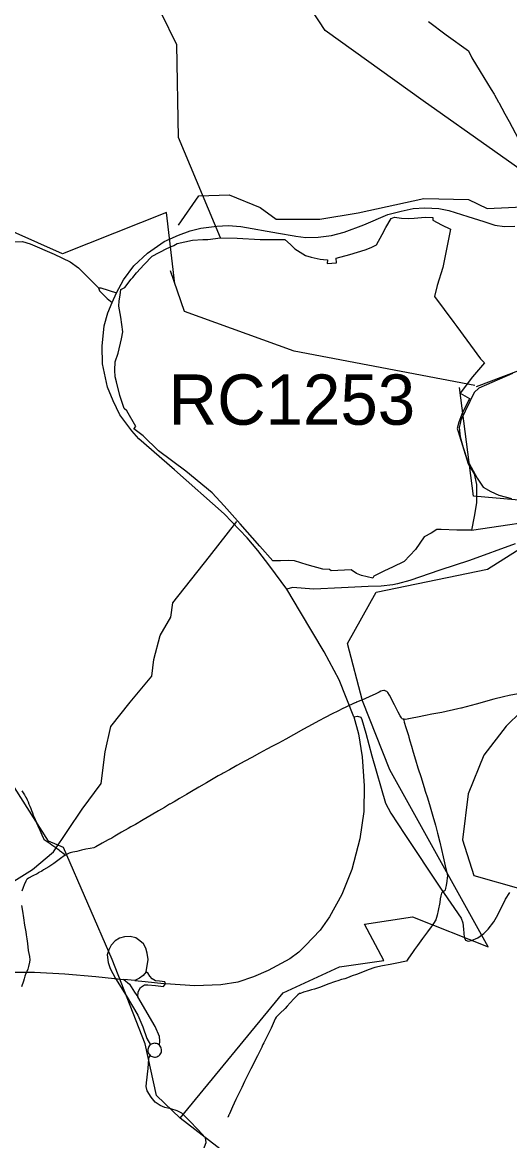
# Model space of a CAD drawing. Extents: x -789162 to -606354, y -1062736 to -945481.
# Drawn here: x -683220 to -681766, y -983825 to -980490 of the extents above; entities that cross this region are included whole.
import ezdxf

# ---------------------------------------------------------------- set-up
doc = ezdxf.new("R2010")
doc.units = 0
for name, color, linetype in [('_SIRSI VZTAHY_CYKLOTRASY MISTNI S', 7, 'Continuous'), ('_SIRSI VZTAHY_SILNICE I TRIDY_NAVRH', 7, 'Continuous'), ('_SIRSI VZTAHY_SILNICE I TRIDY_STAV', 7, 'Continuous'), ('_SIRSI VZTAHY_SILNICE III TRIDY_STAV', 7, 'Continuous'), ('_SIRSI VZTAHY_USES_NRBK_S', 7, 'Continuous'), ('_SIRSI VZTAHY_USES_popis S', 7, 'Continuous'), ('_SIRSI VZTAHY_USES_RBC_S', 7, 'Continuous'), ('_SIRSI VZTAHY_USES_RBK_S', 7, 'Continuous'), ('_SIRSI VZTAHY_VTL PLYNOVOD', 7, 'Continuous')]:
    doc.layers.add(name, color=color, linetype=linetype)

msp = doc.modelspace()

# ---------------------------------------------------------------- linework, layer by layer
at = {"layer": '_SIRSI VZTAHY_CYKLOTRASY MISTNI S'}
for points in [[(-682754.6, -981095.2), (-682693.5, -981007.5), (-682603.3, -981004.8), (-682510.3, -981042), (-682462.5, -981076.6), (-682332.4, -981076.6), (-682218.3, -981058), (-682021.8, -981015.5), (-681889, -981018.1), (-681833.3, -981044.7), (-681705.8, -981039.4), (-681597, -980943.7), (-681607.6, -980869.3)], [(-682765.5, -981269.9), (-682789.8, -981056.7), (-683101, -981179.9), (-683248.1, -981114.9), (-683415.6, -981217.5), (-683554.2, -981298.9)], [(-681869.9, -981573.4), (-682409.1, -981470.4), (-682736.4, -981352.5), (-682778, -981231.3)], [(-682749.1, -983758.6), (-682819.7, -983691.1), (-682854.2, -983537), (-682952.4, -983284.6), (-683097.1, -982950.5), (-683142.3, -982931.9), (-683301.6, -982682.1), (-683245.8, -982381.9), (-683373.3, -982249), (-683399.8, -981898.3), (-683492.8, -981870.4), (-683539.2, -981586.7), (-683511.3, -981493.7), (-683469.5, -981326.4)], [(-681865.1, -981576.1), (-681494, -981436.3), (-681237.5, -981467.1), (-680604.8, -981521.9), (-680563.8, -981648.5), (-680054.3, -981672.4), (-679814.9, -981456.8), (-679476.3, -981614.2), (-679130.9, -981771.7), (-678730.8, -981922.2), (-678395.7, -982024.9)], [(-683584.4, -984928.8), (-683207.4, -984849.1), (-683071.9, -984832.6), (-682972.8, -984387.7), (-683178, -984031.8), (-682844.7, -984024.3), (-682585.3, -984073.3), (-682552.7, -983910), (-682749.1, -983758.6), (-682441.7, -983384.7), (-682273.9, -983306.9), (-682141.1, -983288.3), (-682199.5, -983179.3), (-682055.7, -983157.9), (-681830, -983246.9), (-682123.6, -982719.1), (-682205.7, -982513.8), (-682250.1, -982342.7), (-682164, -982189.3), (-681832.3, -982120.9), (-681534.8, -981932.7), (-681873.7, -981903), (-681915.7, -981578.8)]]:
    msp.add_lwpolyline(points, dxfattribs=at)
at = {"layer": '_SIRSI VZTAHY_SILNICE I TRIDY_NAVRH'}
msp.add_lwpolyline([(-681596.8, -981025.9), (-682024.3, -980723.7), (-682317, -980514.5), (-682437.8, -980328.5), (-682540, -980054.1), (-682540, -979775.1), (-682475, -979510.1), (-682391.3, -979393.8), (-682140.4, -979096.2), (-682001, -978905.6), (-681947.3, -978824.6), (-681923, -978799), (-681877.1, -978779.9), (-681782.6, -978787.7), (-681675.9, -978776.4), (-681489.3, -978689)], dxfattribs=at)
at = {"layer": '_SIRSI VZTAHY_SILNICE I TRIDY_STAV'}
for points in [[(-682939.6, -981296.5), (-682918.2, -981257.7), (-682887.7, -981216.1), (-682846.8, -981177.9), (-682797.6, -981143.3), (-682754.2, -981124.9), (-682719.4, -981112), (-682687.6, -981103.9), (-682640, -981097.5), (-682606.1, -981096.1), (-682568.1, -981098.7), (-682456.2, -981118.9), (-682409.1, -981126.8), (-682404.4, -981127.5), (-682374.2, -981131.4), (-682337.5, -981130.4), (-682297.4, -981125.7), (-682259.5, -981116.1), (-682201.4, -981093.9), (-682129.4, -981063.2), (-682089.8, -981052.6), (-682053.7, -981045.1), (-682019.4, -981043.2), (-681977.7, -981045.5), (-681947.2, -981050.8), (-681890.4, -981069.4), (-681843.3, -981084.2), (-681810.2, -981094.4), (-681781.2, -981098.9), (-681750.9, -981098.2)], [(-682952.1, -981325.6), (-682939.6, -981296.5)], [(-682431, -982180.4), (-682481.7, -982111.9), (-682517.4, -982064.9), (-682549.1, -982027.1), (-682617.8, -981955.9), (-682766.5, -981824.1), (-682872.6, -981732.4), (-682893.9, -981708.2), (-682929.1, -981660.8), (-682949.2, -981618.4), (-682966.2, -981578.4), (-682980.8, -981508.2), (-682982.1, -981455.8), (-682976, -981394.9), (-682965.2, -981356.8), (-682952.1, -981325.6)], [(-682230.7, -982561.4), (-682274.6, -982450.8), (-682319.7, -982367.8), (-682389.8, -982249.4), (-682431, -982180.4)], [(-682230.7, -982561.4), (-682217.6, -982612.4), (-682206.1, -982680.6), (-682200.5, -982766.6), (-682201.7, -982843.4), (-682213.2, -982925.1), (-682236.8, -983016.8), (-682266.7, -983090.8), (-682303.6, -983158.1), (-682332, -983198), (-682375.6, -983242.9), (-682395.3, -983263.1), (-682422.6, -983282.7), (-682487, -983317.4), (-682530.2, -983336.8), (-682577, -983352.2), (-682628.2, -983360.1), (-682705.2, -983363.6), (-682793.3, -983357.4)], [(-682850.5, -983321.9), (-682845.4, -983285.3), (-682847.6, -983266.2), (-682851.4, -983251.2), (-682858.9, -983238.2), (-682869.4, -983229.3), (-682882.2, -983220.7), (-682899.1, -983216.2), (-682915.7, -983217.7), (-682930, -983221.1), (-682943.2, -983229.3), (-682955.2, -983241.8), (-682962.4, -983256.4), (-682966.9, -983271.3), (-682963.8, -983293.6), (-682958.2, -983312.1), (-682942.8, -983341.4), (-682910.7, -983392.6), (-682876.1, -983451), (-682861.1, -983485.6), (-682848.8, -983520.2), (-682838.2, -983539.4)], [(-683337.2, -983322.9), (-683184.5, -983322.7), (-683093.7, -983327.6), (-683001.4, -983335.9), (-682917.1, -983344.4)], [(-682850.5, -983321.9), (-682859.6, -983333.2), (-682870.9, -983340.3), (-682884.2, -983347.7)], [(-682793.3, -983357.4), (-682794.9, -983352), (-682811.5, -983350.1), (-682823.1, -983348.2), (-682833.3, -983343), (-682840.4, -983335.1), (-682844.6, -983326.8), (-682850.5, -983321.9)], [(-682917.1, -983344.4), (-682901, -983358.4), (-682885.6, -983382.5), (-682875.9, -983396.7)], [(-682884.2, -983347.7), (-682917.1, -983344.4)], [(-682884.2, -983347.7), (-682854.1, -983350.2), (-682797.8, -983357.1), (-682793.3, -983357.4)], [(-682875.9, -983396.7), (-682874.3, -983381.7), (-682867.5, -983368.6), (-682856.2, -983361), (-682846.1, -983360.3), (-682823.1, -983362.9), (-682799.4, -983365.2), (-682793.3, -983357.4)], [(-682811.2, -983540.6), (-682809.7, -983527.9), (-682811, -983514.9), (-682823.8, -983485.2), (-682875.9, -983396.7)], [(-682838.2, -983539.4), (-682840.6, -983541.6), (-682842.6, -983544.2), (-682844.2, -983547.1), (-682845.3, -983550.2), (-682845.9, -983553.4), (-682846, -983556.6), (-682845.5, -983559.9), (-682844.6, -983563), (-682843.2, -983565.9), (-682841.3, -983568.6), (-682839.1, -983571)], [(-682811.2, -983540.6), (-682813.7, -983538.6), (-682816.6, -983537), (-682819.6, -983535.8), (-682822.8, -983535.1), (-682826.1, -983535), (-682829.3, -983535.4), (-682832.5, -983536.2), (-682835.5, -983537.6), (-682838.2, -983539.4)], [(-682839.1, -983571), (-682836.2, -983573.1), (-682833, -983574.7), (-682829.6, -983575.7), (-682826.1, -983576.2), (-682822.6, -983576), (-682819.1, -983575.2), (-682815.8, -983573.8), (-682812.8, -983571.9), (-682810.2, -983569.5), (-682808.1, -983566.7), (-682806.4, -983563.6), (-682805.3, -983560.2), (-682804.8, -983556.7), (-682804.9, -983553.1), (-682805.7, -983549.6), (-682807, -983546.3), (-682808.8, -983543.3), (-682811.2, -983540.6)]]:
    msp.add_lwpolyline(points, dxfattribs=at)
at = {"layer": '_SIRSI VZTAHY_SILNICE III TRIDY_STAV'}
for points in [[(-683249.5, -981144.9), (-683220.3, -981143.1), (-683196.9, -981150.9), (-683125.7, -981181.6), (-683077.6, -981204.6), (-683053.3, -981221.7), (-682993.5, -981281.6)], [(-682993.5, -981281.6), (-682990.6, -981290.6), (-682967.7, -981313.2), (-682952.1, -981325.6)], [(-682993.5, -981281.6), (-682986.5, -981281.6), (-682939.6, -981296.5)], [(-681757.8, -981537.2), (-681858.2, -981580.6), (-681872.3, -981593.9), (-681885, -981620.4), (-681911.8, -981676.6), (-681914.2, -981686.4), (-681917.1, -981698.1), (-681913.7, -981725.8), (-681905.2, -981757.5), (-681892.4, -981794.8), (-681863.4, -981849.1), (-681844.9, -981875.9), (-681822.7, -981889.2), (-681798.2, -981899.7), (-681760.5, -981909.8)], [(-681749.7, -982045.3), (-681886.3, -982095.1), (-681974, -982124.1), (-682064.4, -982154.4), (-682100.6, -982164.2), (-682114.9, -982167.1), (-682149.9, -982171.3), (-682188.1, -982172.4), (-682267.8, -982176.2), (-682350.4, -982180), (-682413.8, -982175.1), (-682431, -982180.4)], [(-682230.7, -982561.4), (-682219.8, -982559), (-682210.6, -982562.2), (-682207.4, -982569.5), (-682195.6, -982610), (-682177.7, -982678), (-682136.6, -982818.4), (-682120.4, -982848.3), (-682079.1, -982912.1), (-681972.1, -983072.1), (-681911.2, -983161.4), (-681906.1, -983175.9), (-681903.4, -983194.9), (-681901.8, -983218.9), (-681897.7, -983227.1), (-681890, -983230.4), (-681879.9, -983228.8), (-681860.8, -983220.8), (-681843.4, -983207.4), (-681830.1, -983194.6), (-681813.1, -983172.8), (-681801, -983151.5), (-681778.4, -983104.8), (-681765.3, -983085.5)], [(-682765.6, -984032.8), (-682752.1, -984007), (-682712.8, -983922.5), (-682683.6, -983861.4), (-682671.5, -983831), (-682673.9, -983817.4), (-682696.4, -983792.4), (-682721.4, -983766.7), (-682744.5, -983743.7), (-682758.6, -983735.9), (-682777.7, -983730.9), (-682795.3, -983726), (-682809.3, -983720.4), (-682824.5, -983710.2), (-682836.4, -983695.5), (-682848, -983676.7), (-682850.6, -983663.9), (-682849.9, -983652.4), (-682845, -983609.8), (-682843.1, -983581.5), (-682841.6, -983575.9), (-682839.1, -983571)]]:
    msp.add_lwpolyline(points, dxfattribs=at)
at = {"layer": '_SIRSI VZTAHY_USES_NRBK_S'}
for points in [[(-681879.6, -982004.1), (-681624.2, -981966.8)], [(-683246.3, -983051.8), (-683190.1, -983016.9), (-683127.9, -982963.7), (-683041.5, -982836.2), (-682985.3, -982760.3), (-682973.2, -982666.1), (-682956.5, -982590.2), (-682898.8, -982517.3), (-682833.6, -982439.9), (-682827.5, -982389.8), (-682809.3, -982318.4), (-682777.5, -982263.8), (-682771.4, -982221.3), (-682662.1, -982083.1), (-682580.2, -981978.3)], [(-681686.5, -982501.3), (-681776, -982589.4), (-681842.7, -982675.9), (-681889.8, -982791.3), (-681906.5, -982927.9), (-681873.1, -983034.2), (-681733.1, -983074.5)]]:
    msp.add_lwpolyline(points, dxfattribs=at)
at = {"layer": '_SIRSI VZTAHY_USES_RBC_S'}
msp.add_lwpolyline([(-681943, -981106.7), (-681965.3, -981220.8), (-681982.3, -981274.5), (-681989.9, -981308), (-681933.1, -981385), (-681924.1, -981397.5), (-681853, -981493.9), (-681841.3, -981505.6), (-681876.7, -981547), (-681913.7, -981596.2), (-681885.7, -981612), (-681909, -981659), (-681918, -981682.7), (-681922.5, -981701.7), (-681920, -981710.7), (-681889.5, -981807.1), (-681872, -981836.9), (-681865.5, -981868.2), (-681865.3, -981922.7), (-681872, -981964), (-681879.6, -982004.1), (-681907.3, -982005), (-681924, -982004.6), (-681970.4, -982002.7), (-681983.1, -982002.4), (-682000.3, -982013.6), (-682021.3, -982024), (-682046.9, -982062.2), (-682081.2, -982098.3), (-682115.8, -982114.9), (-682139.6, -982126), (-682171.5, -982142), (-682174.4, -982147.2), (-682208, -982140.2), (-682222.9, -982134.1), (-682239.5, -982123.2), (-682299.2, -982125.7), (-682304.2, -982122.1), (-682323.9, -982120.6), (-682369.9, -982107.8), (-682408.4, -982095.5), (-682427, -982095.3), (-682449.6, -982096.1), (-682472.5, -982096.1), (-682511.5, -982052.5), (-682570.1, -981986.1), (-682618.2, -981931.7), (-682653.5, -981893.4), (-682732.9, -981829), (-682813.7, -981767.8), (-682859.7, -981722.9), (-682887.2, -981702.6), (-682881.4, -981695.6), (-682908.6, -981648.7), (-682916.4, -981641.5), (-682929.1, -981603.1), (-682939.9, -981562.1), (-682943.4, -981547.2), (-682944.7, -981527.3), (-682943.2, -981502.8), (-682934.5, -981476.2), (-682924.5, -981433.9), (-682920.6, -981412.9), (-682926.3, -981369.1), (-682932.2, -981336.9), (-682931.1, -981321), (-682928.6, -981303.9), (-682926, -981286.8), (-682914.8, -981280.5), (-682896, -981256.3), (-682890.9, -981250.5), (-682880.1, -981236.9), (-682857.3, -981212.3), (-682832.5, -981187.5), (-682788.7, -981164.6), (-682768.6, -981155.8), (-682758.5, -981150), (-682712.5, -981139.9), (-682681.7, -981137.2), (-682667.2, -981137.7), (-682629.4, -981132.6), (-682579.1, -981133.9), (-682511.1, -981137.9), (-682473.8, -981137.6), (-682437, -981138), (-682420.2, -981153), (-682407, -981165.8), (-682375.8, -981185.5), (-682358.5, -981189.9), (-682331.6, -981196), (-682322.1, -981197.6), (-682310.1, -981198.1), (-682310.6, -981209.4), (-682282.6, -981207.6), (-682283.6, -981193.5), (-682243.5, -981182), (-682197.4, -981168.3), (-682179.5, -981161.7), (-682171.7, -981157.4), (-682163.8, -981153.1), (-682146.2, -981122.8), (-682135.5, -981102.2), (-682119.4, -981074.5), (-682110.2, -981071), (-682088.6, -981074.1), (-682067.6, -981074.8), (-682051.4, -981074.4), (-682018.7, -981070.8), (-681994.9, -981072.1), (-681995.8, -981080.2), (-681969.4, -981093.5)], close=True, dxfattribs=at)
at = {"layer": '_SIRSI VZTAHY_USES_RBK_S'}
msp.add_lwpolyline([(-682629.4, -981132.6), (-682754.2, -980832.9), (-682759.5, -980556.6), (-682852.4, -980365.3), (-682817.9, -980243), (-682817.9, -980144.7), (-682839.2, -979972), (-682932.1, -979791.3), (-683030.3, -979674.4), (-683025, -979581.4), (-682905.5, -979472.5), (-682759.5, -979371.5), (-682701.1, -979318.4), (-682289.5, -979241.3), (-682167.4, -979087.2), (-682111.6, -978922.5), (-682098.4, -978771), (-682146.2, -978616.9), (-682276.3, -978497.3), (-682409, -978422.9), (-682576.3, -978345.9), (-682687.8, -978311.3), (-682918.8, -978149.3), (-683146.4, -978045)], dxfattribs=at)
at = {"layer": '_SIRSI VZTAHY_VTL PLYNOVOD'}
for points in [[(-682008.2, -980487), (-681955.2, -980527.6), (-681888.6, -980575.2), (-681887.4, -980576.8), (-681887.4, -980576.9), (-681878.9, -980595.3), (-681878.9, -980595.3), (-681853.9, -980636.4), (-681821.4, -980690.1), (-681812.6, -980704.2), (-681811.7, -980705.7), (-681811.7, -980705.7), (-681799.1, -980727.5), (-681798.5, -980728.5), (-681780.2, -980762.9), (-681767.7, -980785.6), (-681730.7, -980855), (-681694.9, -980918.7)], [(-682082.7, -982568.6), (-682086.8, -982566.8), (-682088.2, -982565.8), (-682089.2, -982564.6), (-682093.3, -982558), (-682098.5, -982547.6), (-682109.7, -982525.2), (-682124.9, -982496.6), (-682129.3, -982489), (-682130.6, -982487.6), (-682132.9, -982486), (-682135.5, -982484.6), (-682139.2, -982483.2), (-682141.2, -982483.1), (-682146.7, -982483.6), (-682150.5, -982485.2), (-682155.7, -982487.6), (-682167.9, -982493.2), (-682182.9, -982500.2), (-682198.4, -982507.1), (-682214.9, -982514.5), (-682223.6, -982517.8), (-682223.7, -982517.8), (-682224.5, -982518.1), (-682230.5, -982520.9), (-682230.9, -982521.1), (-682230.9, -982521.1), (-682231.7, -982521.5), (-682237.6, -982524.2), (-682244.8, -982527.7), (-682248.7, -982529.6), (-682254.9, -982532.7), (-682255.2, -982532.9), (-682257.4, -982533.9), (-682263.5, -982536.2), (-682279.2, -982544.2), (-682295.6, -982552.5), (-682316.2, -982563.1), (-682335.6, -982573), (-682355.5, -982583.8), (-682380.9, -982597.8), (-682410.8, -982614.6), (-682434.1, -982627.4), (-682456.3, -982639.6), (-682467.7, -982645.6), (-682474.3, -982649.2), (-682491.2, -982658), (-682512.6, -982669.4), (-682536, -982682.5), (-682556.2, -982693.7), (-682579.8, -982706.8), (-682602, -982719.2), (-682620.8, -982729.7), (-682624.2, -982731.5), (-682624.3, -982731.6), (-682635.7, -982737.7), (-682650.6, -982746.3), (-682670.9, -982757.9), (-682693.6, -982771.4), (-682715.1, -982784.1), (-682730.5, -982793.2), (-682751.2, -982805.2), (-682767.5, -982814.5), (-682780.1, -982821.6), (-682780.8, -982822), (-682796.4, -982831.4), (-682813.8, -982842), (-682835.6, -982854.9), (-682859.6, -982868.7), (-682883, -982881.9), (-682896.5, -982889.5), (-682896.6, -982889.5), (-682904.4, -982893.9), (-682924.5, -982905.5), (-682944.8, -982917.3), (-682953.8, -982922.8), (-682964.2, -982928.2), (-682981.7, -982938.2), (-683001.1, -982949.3), (-683007.3, -982952.1), (-683018, -982954.1), (-683030.9, -982956.3), (-683043.7, -982959.4), (-683058, -982962.6), (-683069.9, -982965.2), (-683077.4, -982966.6), (-683080.7, -982967.7), (-683088.9, -982972.1), (-683091.5, -982973.5), (-683093.7, -982974.6)], [(-681740.4, -982493.1), (-681767.2, -982498.1), (-681784.3, -982501.8), (-681813.4, -982508.6), (-681866.4, -982523.3), (-681896.3, -982531.3), (-681910.3, -982535.1), (-681911.3, -982535.4), (-681920.4, -982537.7), (-681968.9, -982548.1), (-681998.6, -982553.5), (-682017, -982557), (-682041.3, -982562.2), (-682057.4, -982565.4), (-682067.4, -982567.1), (-682067.6, -982567.2), (-682071.7, -982567.8), (-682071.9, -982567.9), (-682076.9, -982568.9), (-682080.8, -982568.7), (-682082.7, -982568.6)], [(-682082.2, -982570.6), (-682082.2, -982570.8), (-682082, -982571.6), (-682080.4, -982576.9), (-682075.6, -982592.8), (-682070, -982610.9), (-682068.2, -982617.1), (-682068.2, -982617.3), (-682067.2, -982622.3), (-682063.8, -982632.8), (-682059.4, -982648.7), (-682054, -982666.7), (-682047, -982690), (-682039.8, -982713.7), (-682030.3, -982742.3), (-682025.1, -982758.8), (-682021.1, -982772.2), (-682021, -982772.3), (-682018.1, -982782.6), (-682011.7, -982802.4), (-682003.7, -982829.5), (-681995.1, -982857.7), (-681987.2, -982884.7), (-681981.1, -982907.9), (-681974.3, -982935.1), (-681969.1, -982956.5), (-681964, -982978.7), (-681958.4, -983005.5), (-681952.7, -983030.9), (-681951.7, -983035), (-681952.2, -983041.8), (-681953.7, -983050.9), (-681956, -983064.1), (-681957.3, -983072.3), (-681958.5, -983078.7), (-681959.1, -983079.2), (-681961.3, -983081.4), (-681967, -983085.5), (-681969.4, -983087), (-681971.2, -983095.3), (-681973.2, -983104.4), (-681974.7, -983114.9), (-681979.5, -983138.7), (-681982.5, -983152.8), (-681986.2, -983166.5), (-681987.9, -983169.9), (-681991.1, -983174.8), (-681997.4, -983183.5), (-682000, -983187.1), (-682010.8, -983202.1), (-682026, -983222.8), (-682041, -983242.8), (-682049.7, -983254.8), (-682049.7, -983254.9), (-682056.1, -983263.8), (-682068.2, -983280.9), (-682074, -983289.6), (-682084.1, -983292.2), (-682097.7, -983295.2), (-682122.3, -983299.6), (-682145.7, -983303.9), (-682168.2, -983308.8), (-682188.5, -983316.3), (-682210.1, -983324.4), (-682222.8, -983329.6), (-682235.9, -983334.1), (-682250.4, -983339.8), (-682258.3, -983342.6), (-682268, -983345), (-682268.2, -983345.1), (-682278.9, -983348.3), (-682286.1, -983350.6), (-682308.9, -983358.8), (-682330.6, -983367.2), (-682348.7, -983373.4), (-682357.8, -983375.2), (-682366.2, -983378.2), (-682381.4, -983382.9), (-682390.4, -983386.1), (-682392.9, -983386.8), (-682398, -983390.4), (-682409.8, -983402.1), (-682421, -983414), (-682429.7, -983423.8), (-682436.4, -983431), (-682451.7, -983446.2), (-682463, -983457.1), (-682465.7, -983461.5), (-682465.7, -983461.6), (-682465.8, -983461.8), (-682468.7, -983468.5), (-682478.1, -983489.4), (-682487.6, -983509.6), (-682499.9, -983533.8), (-682502.7, -983539), (-682503.6, -983540.8), (-682503.7, -983541), (-682505.9, -983546.2), (-682518.2, -983572), (-682538.1, -983610.9), (-682541.4, -983617.4), (-682542.4, -983619.5), (-682557.2, -983649.1), (-682565.6, -983666.3), (-682565.7, -983666.5), (-682565.7, -983666.5), (-682576.3, -983688.8), (-682583, -983702.6), (-682593.6, -983724.4), (-682602.5, -983745.2), (-682603.6, -983747.8), (-682603.7, -983747.9), (-682603.7, -983748), (-682604.3, -983749.3), (-682604.4, -983749.5), (-682604.4, -983749.6), (-682604.8, -983750.3), (-682605.1, -983751.2), (-682605.4, -983751.8), (-682605.5, -983752.1), (-682606, -983753.2), (-682606, -983753.4), (-682606, -983753.4), (-682606.2, -983753.6), (-682606.3, -983753.8), (-682606.4, -983754.1), (-682606.4, -983754.1), (-682606.6, -983754.6), (-682606.7, -983754.6), (-682607.1, -983755.7)], [(-682082.5, -982569.7), (-682082.5, -982569.6), (-682082.7, -982568.6)], [(-682082.2, -982570.6), (-682081.9, -982570.5), (-682081.9, -982570.3), (-682082, -982570.1), (-682082.1, -982569.8), (-682082.1, -982569.6), (-682082.3, -982569.7), (-682082.5, -982569.7)], [(-682082.5, -982569.7), (-682082.3, -982570.2), (-682082.2, -982570.6)], [(-683221.5, -982781.7), (-683217.9, -982787.7), (-683214.2, -982793.7), (-683210.6, -982799.7), (-683210.5, -982799.7), (-683209, -982802.3), (-683206.1, -982808.6), (-683203.3, -982815.1), (-683200.6, -982821.5), (-683198, -982828.1), (-683195.4, -982834.6), (-683192.8, -982841.1), (-683190.3, -982847.7), (-683187.7, -982854.1), (-683185.1, -982860.6), (-683182.3, -982867.2), (-683179.6, -982873.7), (-683176.8, -982880), (-683174, -982886.6), (-683171.3, -982893), (-683168.4, -982899.4), (-683165.7, -982905.8), (-683162.2, -982913.6), (-683157.4, -982924.6), (-683157.2, -982925.1), (-683154.8, -982927.1), (-683149.2, -982930.9), (-683143.4, -982934.8), (-683137.8, -982938.6), (-683132.2, -982942.8), (-683126.6, -982947.3), (-683120.9, -982951.4), (-683118.4, -982953.1), (-683115.1, -982955.4), (-683111, -982958.3), (-683109.3, -982959.5), (-683104, -982963.6), (-683098.7, -982967.7), (-683097.6, -982968.7), (-683094.5, -982973.2), (-683094.1, -982974), (-683094, -982974), (-683093.8, -982974.3)], [(-683094.5, -982975.1), (-683094.6, -982975.2), (-683095.7, -982976), (-683106.3, -982983.7), (-683126.6, -982998.3), (-683141.3, -983008.3), (-683157, -983017.9), (-683162.3, -983021.1), (-683171.4, -983026), (-683172.8, -983027), (-683173.4, -983027.4), (-683176.5, -983029.5), (-683189.4, -983035.9), (-683201.7, -983042.9), (-683205.8, -983045.6), (-683208, -983047.6), (-683210.4, -983051.5), (-683214.9, -983062.8), (-683217.9, -983070.4), (-683221.8, -983080.9)], [(-683094.5, -982975.1), (-683094.5, -982975), (-683094.6, -982974.8), (-683093.8, -982974.3)], [(-683093.7, -982974.6), (-683094.2, -982974.9), (-683094.5, -982975.1)], [(-683093.8, -982974.3), (-683093.8, -982974.5), (-683093.7, -982974.6), (-683093.7, -982974.6)], [(-683222.5, -983123.5), (-683220.1, -983140.8), (-683217.2, -983160.8), (-683213.5, -983182.9), (-683210.4, -983202.5), (-683209, -983211.4), (-683207, -983223.8), (-683205.2, -983237.5), (-683202.6, -983258.2), (-683199.5, -983276.3), (-683198.2, -983285.8), (-683199.5, -983293), (-683202.4, -983306.3), (-683204.5, -983313.8), (-683210.7, -983329.9), (-683211.5, -983331.4), (-683212.5, -983334.9), (-683214.7, -983342.3), (-683214.7, -983342.4), (-683217.1, -983349.7), (-683222.5, -983366.3)]]:
    msp.add_lwpolyline(points, dxfattribs=at)

# ---------------------------------------------------------------- texts
at = {"layer": '_SIRSI VZTAHY_USES_popis S'}
msp.add_text('RC1253', height=150, dxfattribs=at).set_placement((-682784, -981690.1))

doc.saveas('drawing.dxf')
